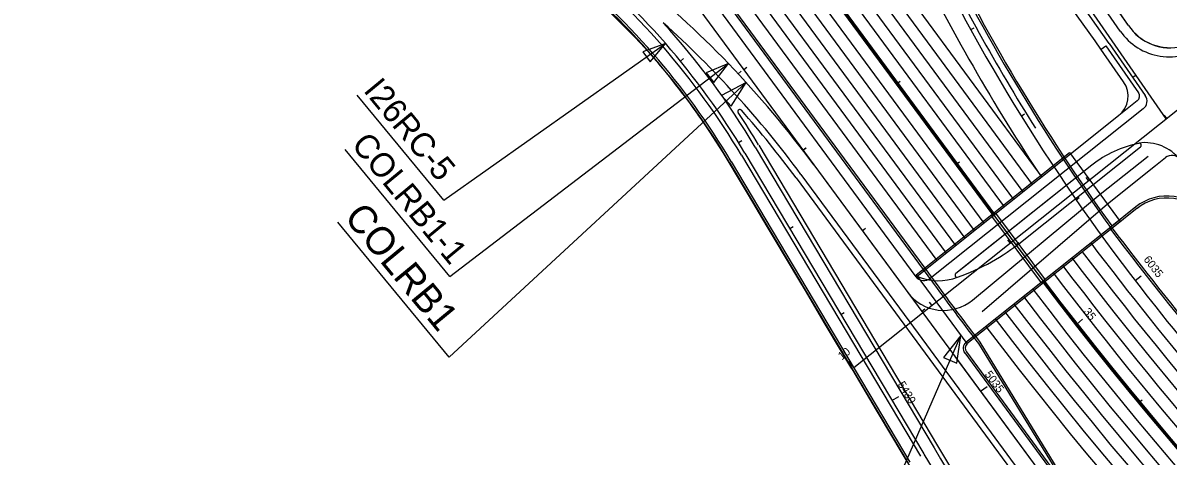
# Model space of a CAD drawing. Extents: x 1944333 to 1975203, y 788957 to 827579.
# Drawn here: x 1970236 to 1971381, y 795717 to 796150 of the extents above; entities that cross this region are included whole.
import ezdxf

# ---------------------------------------------------------------- set-up
doc = ezdxf.new("R2010")
doc.units = 0
for name, color, linetype in [('BR_CENTER LINES', 7, 'Continuous'), ('BR_CONCRETE', 7, 'Continuous'), ('RD_HC_CL_Rel', 7, 'Continuous'), ('RD_HC_Data_Tic_Rel', 7, 'Continuous'), ('RD_HC_TX_Rel_Sta50', 7, 'Continuous'), ('RD_PD_ALT1_LnLine', 7, 'Continuous'), ('RD_PD_ALT1_TrvlWay', 7, 'Continuous'), ('RD_PD_ConcMed', 7, 'Continuous'), ('RD_PD_CstnLmt', 7, 'Continuous'), ('RD_PD_GR', 7, 'Continuous'), ('RD_PD_MedBWall', 7, 'Continuous'), ('RD_PD_PaveShd', 7, 'Continuous'), ('RD_PD_WallFill', 7, 'Continuous'), ('RD_TX_RoadID', 7, 'Continuous')]:
    doc.layers.add(name, color=color, linetype=linetype)

msp = doc.modelspace()

# ---------------------------------------------------------------- linework, layer by layer
at = {"layer": 'BR_CENTER LINES'}
for p, q in [((1971205.7, 795957), (1971207.3, 795958.3)), ((1971206.5, 795957.7), (1971255.5, 795891.9))]:
    msp.add_line(p, q, dxfattribs=at)
at = {"layer": 'BR_CONCRETE'}
for p, q in [((1971128.8, 795897.9), (1971282.2, 796020)), ((1971129.8, 795896.6), (1971283.2, 796018.7)), ((1971282.2, 796020), (1971332.8, 795951.3)), ((1971204.2, 795956.5), (1971208.1, 795959.6)), ((1971208.1, 795959.6), (1971257.8, 795893)), ((1971178.5, 795830.6), (1971331.9, 795952.7)), ((1971179.5, 795829.3), (1971332.8, 795951.3)), ((1971204.2, 795956.5), (1971253.8, 795889.9)), ((1971128.8, 795897.9), (1971179.5, 795829.3)), ((1971253.8, 795889.9), (1971257.8, 795893))]:
    msp.add_line(p, q, dxfattribs=at)
at = {"layer": 'RD_HC_CL_Rel'}
for p, q in [((1970235.6, 797274.6), (1971221.4, 795937.4)), ((1970616, 796564.6), (1971026.4, 796007.8)), ((1971378.8, 796053.9), (1971291.9, 796179.1)), ((1971066.3, 795805.3), (1971453, 796113.1)), ((1970957.5, 796019.4), (1971136.4, 795719)), ((1971026.4, 796007.8), (1971135.3, 795860.1)), ((1971135.3, 795860.1), (1971532.1, 795321.9))]:
    msp.add_line(p, q, dxfattribs=at)
for centre, radius, start, end in [((1972899.9, 797089), 1960, 205.75, 218.6115), ((1970309.6, 795633.8), 754, 30.7638, 51.3903), ((1970211.8, 795407.3), 1012, 36.3977, 51.3903), ((1974296, 798203.9), 3819.7, 216.3977, 243.9112), ((1972851.5, 796739.9), 1996, 210.7638, 246.9227)]:
    msp.add_arc(centre, radius, start, end, dxfattribs=at)
at = {"layer": 'RD_HC_Data_Tic_Rel'}
for p, q in [((1971183.3, 796142.9), (1971186.8, 796144.8)), ((1970893.1, 796111.4), (1970896.2, 796113.9)), ((1970950.9, 796098.7), (1970953.8, 796101.4)), ((1970956.3, 796103), (1970959.5, 796105.3)), ((1971348.6, 796097.5), (1971345.3, 796095.2)), ((1971109.6, 796089), (1971112.9, 796091.4)), ((1971233.8, 796056.6), (1971237.2, 796058.7)), ((1971379.4, 796054.4), (1971376.9, 796057.5)), ((1970951.1, 796030), (1970954.5, 796032.1)), ((1971015.5, 796022.4), (1971018.6, 796024.8)), ((1971015.6, 796022.5), (1971018.8, 796024.8)), ((1971169, 796008.5), (1971172.2, 796010.9)), ((1971301.1, 795992.1), (1971298.6, 795995.2)), ((1971288.6, 795973), (1971291.9, 795975.3)), ((1971002.3, 795944.1), (1971005.8, 795946.2)), ((1971074.9, 795942), (1971078.1, 795944.4)), ((1971222.9, 795929.8), (1971220.4, 795932.9)), ((1971228.3, 795928.1), (1971231.5, 795930.4)), ((1971347.6, 795892.3), (1971353.9, 795897.1)), ((1971144.6, 795867.5), (1971142.1, 795870.7)), ((1971053.5, 795858.2), (1971056.9, 795860.3)), ((1971134.3, 795861.5), (1971137.5, 795863.9)), ((1971289, 795848.5), (1971295.2, 795853.5)), ((1971066.4, 795805.3), (1971061.4, 795811.5)), ((1971104.6, 795772.3), (1971111.5, 795776.4)), ((1971193.2, 795781.6), (1971199.6, 795786.4)), ((1971351.6, 795770.6), (1971354.7, 795773.2))]:
    msp.add_line(p, q, dxfattribs=at)
at = {"layer": 'RD_PD_ALT1_LnLine'}
for p, q in [((1970515.8, 796956.9), (1971235.5, 795980.7)), ((1970506.2, 796949.8), (1971226.1, 795973.2)), ((1970456.3, 796913), (1971177.5, 795934.6)), ((1970465.9, 796920.1), (1971186.9, 795942.1)), ((1970446.6, 796905.8), (1971168.1, 795927.1)), ((1970636.3, 796813.6), (1971204.2, 796043.4)), ((1971204.2, 796043.4), (1971244.9, 795988.2)), ((1971312.9, 795978.4), (1971360.6, 796016.4)), ((1971026.4, 796007.8), (1971115.7, 795886.6)), ((1971250.6, 796000.6), (1971254.2, 795995.7)), ((1971185, 795872.7), (1971312.9, 795978.4))]:
    msp.add_line(p, q, dxfattribs=at)
for centre, radius, start, end in [((1971357.3, 795985), 45, 38.2884, 97.4352), ((1974296, 798203.9), 3758.7, 217.2297, 223.1115), ((1974296, 798203.9), 3782.7, 217.2379, 225.5447), ((1974296, 798203.9), 3770.7, 217.2585, 225.5447), ((1974296, 798203.9), 3794.7, 217.2419, 225.5447), ((1971150.9, 795946.1), 54, 247.2375, 290.9668), ((1971156.3, 795907.4), 45, 216.3977, 309.5898), ((1974296, 798203.9), 3856.7, 217.2624, 243.9112), ((1974296, 798203.9), 3844.7, 217.2585, 243.9112), ((1974296, 798203.9), 3868.7, 217.2663, 243.9112)]:
    msp.add_arc(centre, radius, start, end, dxfattribs=at)
at = {"layer": 'RD_PD_ALT1_TrvlWay'}
for p, q in [((1970496.5, 796942.6), (1971216.7, 795965.8)), ((1970475.6, 796927.2), (1971196.3, 795949.6)), ((1970436.9, 796898.7), (1971158.7, 795919.6)), ((1970646, 796820.8), (1971250.6, 796000.6)), ((1971332.8, 796141.4), (1970982.1, 796646.7)), ((1970628.8, 796574), (1971128.6, 795896.1)), ((1970616, 796564.6), (1971026.4, 796007.8)), ((1971321.8, 796129.1), (1971357.8, 796077.2)), ((1971355.8, 796063.7), (1971142.9, 795894.3)), ((1970954.1, 796017.4), (1971133, 795716.9)), ((1970967.8, 796025.6), (1971146.7, 795725.1)), ((1971320, 795968.8), (1971368.1, 796007)), ((1971368.1, 796007), (1971378.2, 796015.1)), ((1971013.5, 795998.3), (1971122.4, 795850.6)), ((1971194.8, 795861.3), (1971320, 795968.8)), ((1971122.4, 795850.6), (1971519.2, 795312.4)), ((1971167.4, 795816.5), (1971532.1, 795321.9))]:
    msp.add_line(p, q, dxfattribs=at)
for centre, radius, start, end in [((1969897.2, 795140.5), 1734, 34.7587, 46.4244), ((1972899.9, 797089), 1976, 205.75, 213.4208), ((1970309.6, 795633.8), 750, 30.7638, 51.3903), ((1970211.8, 795407.3), 1012, 36.3977, 51.3903), ((1970211.8, 795407.3), 996, 36.3977, 48.1824), ((1970309.6, 795633.8), 766, 30.7638, 42.3284), ((1971382.1, 796175.6), 60, 214.7587, 307.4711), ((1971349.6, 796071.5), 10, 308.5157, 34.7587), ((1971384.4, 796007.3), 10, 34.7587, 128.5157), ((1971136.6, 795902.1), 10, 216.3977, 308.5157), ((1974296, 798203.9), 3806.7, 217.2459, 225.5447), ((1974296, 798203.9), 3832.7, 217.2545, 243.9112), ((1974296, 798203.9), 3746.7, 218.6115, 223.1115), ((1974296, 798203.9), 3880.7, 217.2701, 243.9112), ((1972851.5, 796739.9), 1984, 210.7638, 234.3208)]:
    msp.add_arc(centre, radius, start, end, dxfattribs=at)
at = {"layer": 'RD_PD_ConcMed'}
for p, q in [((1971234.6, 795931.5), (1971353.1, 796025.8)), ((1971234.6, 795931.5), (1971353.1, 796025.8)), ((1971304.4, 796007.5), (1971168.3, 795899.2))]:
    msp.add_line(p, q, dxfattribs=at)
msp.add_lwpolyline([(1971304.4, 796007.5), (1971176.1, 795905.3), (1971168.3, 795899.2)], dxfattribs=at)
for centre, radius, start, end in [((1971372.9, 795921.4), 110, 101.2496, 128.5157), ((1971372.9, 795921.4), 110, 101.2496, 128.5157), ((1971351.9, 796027.4), 2, 308.5157, 101.2496), ((1971351.9, 796027.4), 2, 308.5157, 101.2496), ((1971099.6, 796098.8), 215, 289.1874, 308.9119), ((1971099.6, 796098.8), 215, 289.1874, 308.9119), ((1971169.6, 795897.6), 2, 128.5157, 289.1874), ((1971169.6, 795897.6), 2, 128.5157, 289.1874)]:
    msp.add_arc(centre, radius, start, end, dxfattribs=at)
at = {"layer": 'RD_PD_CstnLmt'}
msp.add_lwpolyline([(1970812.3, 796170.7), (1970846.6, 796136.3), (1970853.4, 796129), (1970853.4, 796129), (1970856.5, 796125.6), (1970859.8, 796121.9), (1970863, 796118.3), (1970866.2, 796114.6), (1970869.4, 796110.9), (1970872.5, 796107.2), (1970875.7, 796103.4), (1970878.8, 796099.6), (1970881.8, 796095.9), (1970884.9, 796092.1), (1970887.9, 796088.2), (1970890.9, 796084.4), (1970893.9, 796080.5), (1970896.8, 796076.6), (1970899.8, 796072.7), (1970902.7, 796068.8), (1970905.5, 796064.9), (1970908.4, 796060.9), (1970910.1, 796058.4), (1970910.1, 796058.4), (1970911.2, 796056.9), (1970914, 796052.9), (1970916.8, 796048.9), (1970919.5, 796044.9), (1970922.2, 796040.8), (1970935.4, 796020.3), (1970935.4, 796020.3), (1970956.8, 795984.5), (1970960.9, 795977.7), (1970979.5, 795946.3), (1970986.4, 795934.7), (1971012, 795891.7), (1971017.7, 795882.2), (1971037.6, 795848.7), (1971039.5, 795845.5), (1971063.2, 795805.8), (1971065.3, 795802.3), (1971088.7, 795762.8), (1971091.7, 795757.9), (1971114.3, 795719.9), (1971140.4, 795676.8)], dxfattribs=at)
at = {"layer": 'RD_PD_GR'}
for p, q in [((1970990.3, 796652.4), (1971340.9, 796147.1)), ((1971336.2, 796090.8), (1971313.5, 796123.4)), ((1971283.2, 796018.7), (1971331.2, 796057))]:
    msp.add_line(p, q, dxfattribs=at)
for centre, radius, start, end in [((1969897.2, 795140.5), 1724, 34.7587, 45.6209), ((1971382.9, 796175.3), 50.5, 213.8568, 283.996), ((1971315.7, 796076.5), 25, 308.5157, 34.8162), ((1974296, 798203.9), 3732.7, 217.2515, 219.5714)]:
    msp.add_arc(centre, radius, start, end, dxfattribs=at)
at = {"layer": 'RD_PD_MedBWall'}
for p, q in [((1970485.2, 796934.3), (1971205.4, 795957.4)), ((1970486.9, 796935.5), (1971207, 795958.7)), ((1971178.5, 795830.6), (1971179.7, 795829)), ((1971177.4, 795819.9), (1971294.1, 795661.5)), ((1971179, 795821), (1971295.7, 795662.7))]:
    msp.add_line(p, q, dxfattribs=at)
for centre, radius, start, end in [((1974296, 798203.9), 3820.7, 217.2581, 243.9112), ((1974296, 798203.9), 3818.7, 217.2574, 243.9112), ((1971183.8, 795824.6), 8, 131.4818, 216.3977), ((1971183.8, 795824.6), 6, 133.1759, 216.3977)]:
    msp.add_arc(centre, radius, start, end, dxfattribs=at)
at = {"layer": 'RD_PD_PaveShd'}
for p, q in [((1971341, 796147.1), (1970990.3, 796652.4)), ((1970675.5, 796554.9), (1971149.3, 795912.2)), ((1971313.6, 796123.4), (1971318.5, 796126.8)), ((1971318.5, 796126.8), (1971351.1, 796079.9)), ((1971349.9, 796071.8), (1971283, 796018.5)), ((1970971.3, 796027.6), (1971150.1, 795727.1)), ((1971008.7, 795994.7), (1971514.4, 795308.8))]:
    msp.add_line(p, q, dxfattribs=at)
for centre, radius, start, end in [((1972901, 797086.5), 1954, 205.75, 212.2292), ((1971382.6, 796174.6), 49.9, 213.4478, 284.4588), ((1971346.1, 796076.5), 6, 308.5157, 34.7587), ((1970952.5, 796061.2), 2, 33.6168, 213.6168), ((1970211.8, 795407.3), 990, 36.3977, 41.4229), ((1970309.6, 795633.8), 770, 30.7638, 33.6168), ((1974296, 798203.9), 3734.7, 217.2214, 223.1156), ((1974296, 798203.9), 3892.7, 217.274, 242.8933), ((1972851.5, 796739.9), 1980, 210.7638, 228.8892)]:
    msp.add_arc(centre, radius, start, end, dxfattribs=at)
at = {"layer": 'RD_PD_WallFill'}
for p, q in [((1970636.9, 796580), (1971149.6, 795884.4)), ((1970638.5, 796581.2), (1971151.3, 795885.6)), ((1970942.1, 796010.2), (1971120.9, 795709.7)), ((1970943.8, 796011.3), (1971122.6, 795710.8)), ((1971349.8, 795964.4), (1971324, 795943.8)), ((1971348.4, 795965.8), (1971324.4, 795946.7)), ((1971191, 795829.4), (1971294.1, 795661.5)), ((1971295.7, 795662.7), (1971192.6, 795830.6))]:
    msp.add_line(p, q, dxfattribs=at)
for centre, radius, start, end in [((1972899.9, 797089), 1948, 205.75, 216.0047), ((1972899.9, 797089), 1946, 205.75, 215.9432), ((1970309.6, 795633.8), 736, 30.7638, 52.2411), ((1970309.6, 795633.8), 738, 30.7638, 51.4626), ((1971379.5, 795926.7), 50, 34.7587, 128.5152), ((1971379.5, 795926.7), 48, 34.7587, 128.5152), ((1974296, 798203.9), 3908.9, 216.3977, 217.4067), ((1974296, 798203.9), 3906.9, 216.3977, 217.4067)]:
    msp.add_arc(centre, radius, start, end, dxfattribs=at)
at = {"layer": 'RD_TX_RoadID'}
for p, q in [((1970656.6, 795972.5), (1970569.9, 796077.4)), ((1970662.5, 795896.3), (1970557.8, 796023.2)), ((1970661.9, 795815.8), (1970550.5, 795950.7))]:
    msp.add_line(p, q, dxfattribs=at)
for points in [[(1970656.6, 795972.5), (1970878.2, 796129)], [(1970662.5, 795896.3), (1970941.1, 796108.9)], [(1970661.9, 795815.8), (1970958.8, 796090)], [(1971040, 795530.6), (1971173.5, 795837.3)]]:
    msp.add_lwpolyline(points, dxfattribs=at)
for points in [[(1970862.8, 796110.6), (1970878.2, 796129), (1970855.6, 796120.7)], [(1970926.4, 796089.9), (1970941.1, 796108.9), (1970918.9, 796099.8)], [(1970943.9, 796066.3), (1970958.8, 796090), (1970934.1, 796077)], [(1971169.4, 795809.7), (1971173.5, 795837.3), (1971156.1, 795815.4)]]:
    msp.add_lwpolyline(points, close=True, dxfattribs=at)

# ---------------------------------------------------------------- texts
at = {"layer": 'RD_HC_TX_Rel_Sta50'}
for s, rotation, p in [('6035', 307.6302, (1971355.7, 795913.2)), ('35', 308.0714, (1971295.7, 795861)), ('10', 38.5157, (1971054.5, 795812.4)), ('5035', 306.3977, (1971196.9, 795798.5)), ('5430', 300.7638, (1971110, 795788.7))]:
    msp.add_text(s, height=8, rotation=rotation, dxfattribs=at).set_placement(p)
at = {"layer": 'RD_TX_RoadID'}
for s, height, p in [('I26RC-5  ', 24, (1970575.3, 796081.9)), ('COLRB1-1 ', 24, (1970563.2, 796027.6)), ('COLRB1  ', 28, (1970555.9, 795955.1))]:
    msp.add_text(s, height=height, rotation=309.5517, dxfattribs=at).set_placement(p)

doc.saveas('drawing.dxf')
